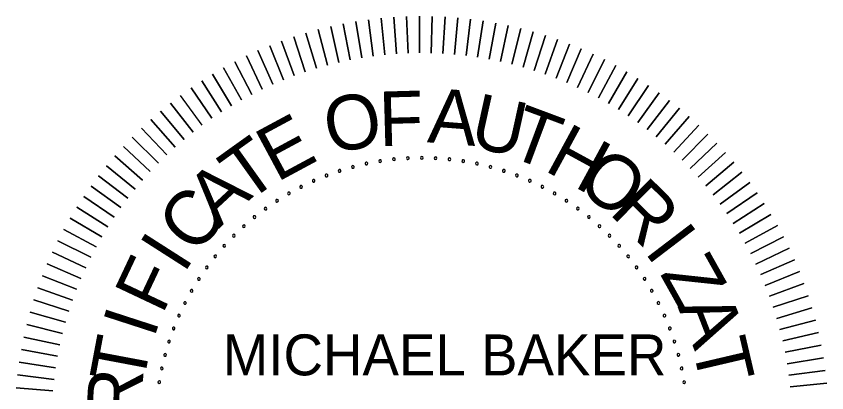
# Model space of a CAD drawing. Extents: x 172 to 3385, y 73 to 2074.
# Drawn here: x 2779.9 to 3027.7, y 536.9 to 651.9 of the extents above; entities that cross this region are included whole.
import ezdxf

# ---------------------------------------------------------------- set-up
doc = ezdxf.new("R2010")
doc.units = 0
doc.layers.add('G-ANNO-TEXT', color=7, linetype='Continuous')

msp = doc.modelspace()

# ---------------------------------------------------------------- linework, layer by layer
at = {"layer": 'G-ANNO-TEXT'}
for points in [[(2899.68, 640.55), (2899.27, 651.77)], [(2899.27, 651.77), (2899.68, 640.55)], [(2903.24, 640.63), (2903.18, 651.85)], [(2903.18, 651.85), (2903.24, 640.63)], [(2906.8, 640.59), (2907.09, 651.81)], [(2907.09, 651.81), (2906.8, 640.59)], [(2910.35, 640.44), (2910.99, 651.65)], [(2910.99, 651.65), (2910.35, 640.44)], [(2882.04, 638.5), (2879.87, 649.52)], [(2879.87, 649.52), (2882.04, 638.5)], [(2885.54, 639.14), (2883.72, 650.21)], [(2883.72, 650.21), (2885.54, 639.14)], [(2889.05, 639.66), (2887.59, 650.78)], [(2887.59, 650.78), (2889.05, 639.66)], [(2892.59, 640.07), (2891.47, 651.23)], [(2891.47, 651.23), (2892.59, 640.07)], [(2896.13, 640.37), (2895.36, 651.56)], [(2895.36, 651.56), (2896.13, 640.37)], [(2913.9, 640.19), (2914.89, 651.36)], [(2914.89, 651.36), (2913.9, 640.19)], [(2917.43, 639.81), (2918.78, 650.96)], [(2918.78, 650.96), (2917.43, 639.81)], [(2920.96, 639.33), (2922.65, 650.43)], [(2922.65, 650.43), (2920.96, 639.33)], [(2924.46, 638.74), (2926.51, 649.78)], [(2926.51, 649.78), (2924.46, 638.74)], [(2871.68, 635.96), (2868.49, 646.72)], [(2868.49, 646.72), (2871.68, 635.96)], [(2875.1, 636.91), (2872.25, 647.77)], [(2872.25, 647.77), (2875.1, 636.91)], [(2878.56, 637.76), (2876.05, 648.7)], [(2876.05, 648.7), (2878.56, 637.76)], [(2927.95, 638.04), (2930.34, 649.01)], [(2930.34, 649.01), (2927.95, 638.04)], [(2931.41, 637.23), (2934.14, 648.11)], [(2934.14, 648.11), (2931.41, 637.23)], [(2934.85, 636.31), (2937.92, 647.1)], [(2937.92, 647.1), (2934.85, 636.31)], [(2864.93, 633.72), (2861.06, 644.26)], [(2861.06, 644.26), (2864.93, 633.72)], [(2868.28, 634.89), (2864.76, 645.55)], [(2864.76, 645.55), (2868.28, 634.89)], [(2938.26, 635.28), (2941.66, 645.97)], [(2941.66, 645.97), (2938.26, 635.28)], [(2941.63, 634.15), (2945.37, 644.73)], [(2945.37, 644.73), (2941.63, 634.15)], [(2861.6, 632.45), (2857.42, 642.86)], [(2857.42, 642.86), (2861.6, 632.45)], [(2944.96, 632.91), (2949.03, 643.37)], [(2949.03, 643.37), (2944.96, 632.91)], [(2948.25, 631.57), (2952.65, 641.89)], [(2952.65, 641.89), (2948.25, 631.57)], [(2855.09, 629.58), (2850.26, 639.71)], [(2850.26, 639.71), (2855.09, 629.58)], [(2858.33, 631.07), (2853.81, 641.34)], [(2853.81, 641.34), (2858.33, 631.07)], [(2951.5, 630.12), (2956.23, 640.3)], [(2956.23, 640.3), (2951.5, 630.12)], [(2851.91, 628), (2846.76, 637.97)], [(2846.76, 637.97), (2851.91, 628)], [(2954.71, 628.57), (2959.75, 638.6)], [(2959.75, 638.6), (2954.71, 628.57)], [(2957.86, 626.93), (2963.21, 636.79)], [(2963.21, 636.79), (2957.86, 626.93)], [(2848.77, 626.32), (2843.31, 636.12)], [(2843.31, 636.12), (2848.77, 626.32)], [(2960.96, 625.18), (2966.62, 634.87)], [(2966.62, 634.87), (2960.96, 625.18)], [(2842.67, 622.67), (2836.61, 632.11)], [(2836.61, 632.11), (2842.67, 622.67)], [(2845.69, 624.54), (2839.93, 634.17)], [(2839.93, 634.17), (2845.69, 624.54)], [(2964, 623.34), (2969.96, 632.85)], [(2969.96, 632.85), (2964, 623.34)], [(2839.71, 620.7), (2833.35, 629.94)], [(2833.35, 629.94), (2839.71, 620.7)], [(2966.99, 621.41), (2973.24, 630.72)], [(2973.24, 630.72), (2966.99, 621.41)], [(2836.81, 618.63), (2830.16, 627.68)], [(2969.91, 619.38), (2976.45, 628.49)], [(2976.45, 628.49), (2969.91, 619.38)], [(2833.98, 616.48), (2827.05, 625.31)], [(2827.05, 625.31), (2833.98, 616.48)], [(2972.76, 617.26), (2979.59, 626.16)], [(2979.59, 626.16), (2972.76, 617.26)], [(2831.22, 614.24), (2824.01, 622.85)], [(2824.01, 622.85), (2831.22, 614.24)], [(2975.55, 615.05), (2982.66, 623.74)], [(2982.66, 623.74), (2975.55, 615.05)], [(2828.52, 611.92), (2821.06, 620.3)], [(2821.06, 620.3), (2828.52, 611.92)], [(2978.27, 612.75), (2985.64, 621.21)], [(2985.64, 621.21), (2978.27, 612.75)], [(2825.91, 609.51), (2818.18, 617.65)], [(2818.18, 617.65), (2825.91, 609.51)], [(2988.55, 618.6), (2980.91, 610.37)], [(2980.91, 610.37), (2988.55, 618.6)], [(2823.37, 607.02), (2815.39, 614.91)], [(2815.39, 614.91), (2823.37, 607.02)], [(2991.37, 615.89), (2983.48, 607.91)], [(2983.48, 607.91), (2991.37, 615.89)], [(2820.91, 604.45), (2812.68, 612.09)], [(2812.68, 612.09), (2820.91, 604.45)], [(2994.11, 613.1), (2985.97, 605.37)], [(2985.97, 605.37), (2994.11, 613.1)], [(2996.75, 610.22), (2988.38, 602.76)], [(2988.38, 602.76), (2996.75, 610.22)], [(2818.53, 601.81), (2810.07, 609.18)], [(2810.07, 609.18), (2818.53, 601.81)], [(2999.31, 607.27), (2990.7, 600.06)], [(2990.7, 600.06), (2999.31, 607.27)], [(2816.23, 599.09), (2807.55, 606.2)], [(2807.55, 606.2), (2816.23, 599.09)], [(2814.02, 596.3), (2805.12, 603.13)], [(2805.12, 603.13), (2814.02, 596.3)], [(3001.77, 604.23), (2992.94, 597.3)], [(2992.94, 597.3), (3001.77, 604.23)], [(2811.9, 593.45), (2802.79, 599.99)], [(2802.79, 599.99), (2811.9, 593.45)], [(3004.14, 601.12), (2995.09, 594.47)], [(2995.09, 594.47), (3004.14, 601.12)], [(3006.4, 597.93), (2997.15, 591.57)], [(2997.15, 591.57), (3006.4, 597.93)], [(2809.88, 590.53), (2800.56, 596.78)], [(2800.56, 596.78), (2809.88, 590.53)], [(3008.57, 594.67), (2999.12, 588.61)], [(2999.12, 588.61), (3008.57, 594.67)], [(2807.94, 587.54), (2798.43, 593.5)], [(2798.43, 593.5), (2807.94, 587.54)], [(2806.1, 584.5), (2796.41, 590.16)], [(2796.41, 590.16), (2806.1, 584.5)], [(3010.63, 591.35), (3001, 585.59)], [(3001, 585.59), (3010.63, 591.35)], [(3012.58, 587.97), (3002.78, 582.51)], [(3002.78, 582.51), (3012.58, 587.97)], [(2804.35, 581.4), (2794.49, 586.75)], [(2794.49, 586.75), (2804.35, 581.4)], [(2802.71, 578.25), (2792.68, 583.29)], [(2792.68, 583.29), (2802.71, 578.25)], [(3014.43, 584.52), (3004.46, 579.37)], [(3004.46, 579.37), (3014.43, 584.52)], [(3016.17, 581.02), (3006.04, 576.19)], [(3006.04, 576.19), (3016.17, 581.02)], [(2801.16, 575.05), (2790.98, 579.77)], [(2790.98, 579.77), (2801.16, 575.05)], [(3017.8, 577.47), (3007.52, 572.95)], [(3007.52, 572.95), (3017.8, 577.47)], [(2799.71, 571.8), (2789.39, 576.2)], [(2789.39, 576.2), (2799.71, 571.8)], [(2798.37, 568.5), (2787.91, 572.58)], [(2787.91, 572.58), (2798.37, 568.5)], [(3019.31, 573.87), (3008.9, 569.68)], [(3008.9, 569.68), (3019.31, 573.87)], [(3020.72, 570.22), (3010.18, 566.36)], [(3010.18, 566.36), (3020.72, 570.22)], [(2797.13, 565.17), (2786.55, 568.91)], [(2786.55, 568.91), (2797.13, 565.17)], [(2796, 561.8), (2785.31, 565.21)], [(2785.31, 565.21), (2796, 561.8)], [(3022, 566.52), (3011.35, 563)], [(3011.35, 563), (3022, 566.52)], [(3023.17, 562.79), (3012.42, 559.6)], [(3012.42, 559.6), (3023.17, 562.79)], [(2794.97, 558.39), (2784.18, 561.46)], [(2784.18, 561.46), (2794.97, 558.39)], [(2794.05, 554.96), (2783.17, 557.69)], [(2783.17, 557.69), (2794.05, 554.96)], [(3024.23, 559.03), (3013.37, 556.18)], [(3013.37, 556.18), (3024.23, 559.03)], [(3025.16, 555.23), (3014.22, 552.72)], [(3014.22, 552.72), (3025.16, 555.23)], [(2793.24, 551.49), (2782.28, 553.88)], [(2782.28, 553.88), (2793.24, 551.49)], [(3025.97, 551.41), (3014.96, 549.25)], [(3014.96, 549.25), (3025.97, 551.41)], [(2792.54, 548.01), (2781.5, 550.05)], [(2781.5, 550.05), (2792.54, 548.01)], [(2791.95, 544.5), (2780.85, 546.19)], [(2780.85, 546.19), (2791.95, 544.5)], [(3026.67, 547.56), (3015.59, 545.75)], [(3015.59, 545.75), (3026.67, 547.56)], [(3027.24, 543.7), (3016.11, 542.23)], [(3016.11, 542.23), (3027.24, 543.7)], [(2791.47, 540.98), (2780.32, 542.32)], [(2780.32, 542.32), (2791.47, 540.98)], [(2791.1, 537.44), (2779.92, 538.43)], [(2779.92, 538.43), (2791.1, 537.44)], [(3027.69, 539.81), (3016.52, 538.69)], [(3016.52, 538.69), (3027.69, 539.81)]]:
    msp.add_lwpolyline(points, dxfattribs=at)
for centre, start, end in [((2886.98, 606.85), 12, 192), ((2891.16, 607.63), 9, 189), ((2891.16, 607.63), 189, 9), ((2895.38, 608.18), 6, 186), ((2895.38, 608.18), 186, 6), ((2899.62, 608.51), 3, 183), ((2899.62, 608.51), 183, 3), ((2903.87, 608.63), 0, 180), ((2903.87, 608.63), 180, 0), ((2908.12, 608.51), 357, 177), ((2908.12, 608.51), 177, 357), ((2912.36, 608.18), 354, 174), ((2912.36, 608.18), 174, 354), ((2916.57, 607.63), 351, 171), ((2916.57, 607.63), 171, 351), ((2920.76, 606.85), 348, 168), ((2878.77, 604.65), 18, 198), ((2878.77, 604.65), 198, 18), ((2882.85, 605.86), 15, 195), ((2882.85, 605.86), 195, 15), ((2886.98, 606.85), 192, 12), ((2920.76, 606.85), 168, 348), ((2924.89, 605.86), 165, 345), ((2924.89, 605.86), 345, 165), ((2928.97, 604.65), 162, 342), ((2928.97, 604.65), 342, 162), ((2874.76, 603.23), 21, 201), ((2874.76, 603.23), 201, 21), ((2932.97, 603.23), 159, 339), ((2932.97, 603.23), 339, 159), ((2867, 599.77), 27, 207), ((2867, 599.77), 207, 27), ((2870.84, 601.6), 24, 204), ((2870.84, 601.6), 204, 24), ((2936.9, 601.6), 156, 336), ((2936.9, 601.6), 336, 156), ((2940.74, 599.77), 153, 333), ((2940.74, 599.77), 333, 153), ((2863.26, 597.75), 30, 210), ((2863.26, 597.75), 210, 30), ((2944.48, 597.75), 150, 330), ((2944.48, 597.75), 330, 150), ((2859.64, 595.52), 33, 213), ((2859.64, 595.52), 213, 33), ((2948.1, 595.52), 147, 327), ((2948.1, 595.52), 327, 147), ((2856.13, 593.12), 36, 216), ((2856.13, 593.12), 216, 36), ((2951.61, 593.12), 144, 324), ((2951.61, 593.12), 324, 144), ((2852.76, 590.53), 39, 219), ((2852.76, 590.53), 219, 39), ((2954.98, 590.53), 141, 321), ((2954.98, 590.53), 321, 141), ((2849.53, 587.77), 42, 222), ((2849.53, 587.77), 222, 42), ((2958.21, 587.77), 138, 318), ((2958.21, 587.77), 318, 138), ((2846.44, 584.84), 45, 225), ((2846.44, 584.84), 225, 45), ((2961.3, 584.84), 135, 315), ((2961.3, 584.84), 315, 135), ((2843.52, 581.75), 48, 228), ((2843.52, 581.75), 228, 48), ((2964.22, 581.75), 132, 312), ((2964.22, 581.75), 312, 132), ((2840.75, 578.52), 51, 231), ((2840.75, 578.52), 231, 51), ((2966.99, 578.52), 129, 309), ((2966.99, 578.52), 309, 129), ((2838.17, 575.15), 54, 234), ((2838.17, 575.15), 234, 54), ((2969.57, 575.15), 126, 306), ((2969.57, 575.15), 306, 126), ((2835.76, 571.64), 57, 237), ((2835.76, 571.64), 237, 57), ((2971.98, 571.64), 123, 303), ((2971.98, 571.64), 303, 123), ((2833.54, 568.02), 60, 240), ((2833.54, 568.02), 240, 60), ((2974.2, 568.02), 120, 300), ((2974.2, 568.02), 300, 120), ((2831.51, 564.28), 63, 243), ((2831.51, 564.28), 243, 63), ((2976.23, 564.28), 117, 297), ((2976.23, 564.28), 297, 117), ((2829.68, 560.44), 66, 246), ((2829.68, 560.44), 246, 66), ((2978.06, 560.44), 114, 294), ((2978.06, 560.44), 294, 114), ((2828.05, 556.52), 69, 249), ((2828.05, 556.52), 249, 69), ((2979.69, 556.52), 111, 291), ((2979.69, 556.52), 291, 111), ((2826.63, 552.51), 72, 252), ((2826.63, 552.51), 252, 72), ((2981.11, 552.51), 108, 288), ((2981.11, 552.51), 288, 108), ((2825.42, 548.43), 75, 255), ((2825.42, 548.43), 255, 75), ((2982.32, 548.43), 105, 285), ((2982.32, 548.43), 285, 105), ((2824.43, 544.3), 78, 258), ((2824.43, 544.3), 258, 78), ((2983.31, 544.3), 102, 282), ((2983.31, 544.3), 282, 102), ((2823.65, 540.12), 81, 261), ((2823.65, 540.12), 261, 81), ((2984.08, 540.12), 99, 279), ((2984.08, 540.12), 279, 99)]:
    msp.add_arc(centre, 0.417, start, end, dxfattribs=at)

# ---------------------------------------------------------------- texts
for s, rotation, p in [('A', 355.5955, (2905.39, 613.37)), ('O', 10.7295, (2875.71, 609.74)), ('F', 1.5867, (2890.94, 612.14)), ('U', 347.5481, (2918, 612.18)), ('T', 339.5007, (2929.64, 609.4)), ('E', 28.279, (2859.53, 601.01)), ('H', 331.4533, (2940.94, 604.94)), ('T', 35.5725, (2850.22, 594.55)), ('O', 323.4059, (2950.51, 599.67)), ('A', 42.8659, (2841.76, 586.85)), ('R', 315.3585, (2960.83, 591.77)), ('C', 50.1594, (2834.75, 578.52)), ('I', 307.3112, (2971.67, 580.03)), ('I', 57.4529, (2831.12, 572.95)), ('Z', 299.2638, (2976.56, 573.24)), ('F', 64.7464, (2824.58, 560.48)), ('A', 291.2164, (2982.03, 563.21)), ('I', 72.0398, (2822, 553.16)), ('T', 79.3333, (2818.69, 538.8)), ('T', 283.169, (2986.39, 551.42)), ('R', 86.6268, (2817.92, 527.78))]:
    msp.add_text(s, height=16.67, rotation=rotation, dxfattribs=at).set_placement(p)
msp.add_text('MICHAEL BAKER', height=12.5016, dxfattribs=at).set_placement((2843.04, 542.19))

doc.saveas('drawing.dxf')
